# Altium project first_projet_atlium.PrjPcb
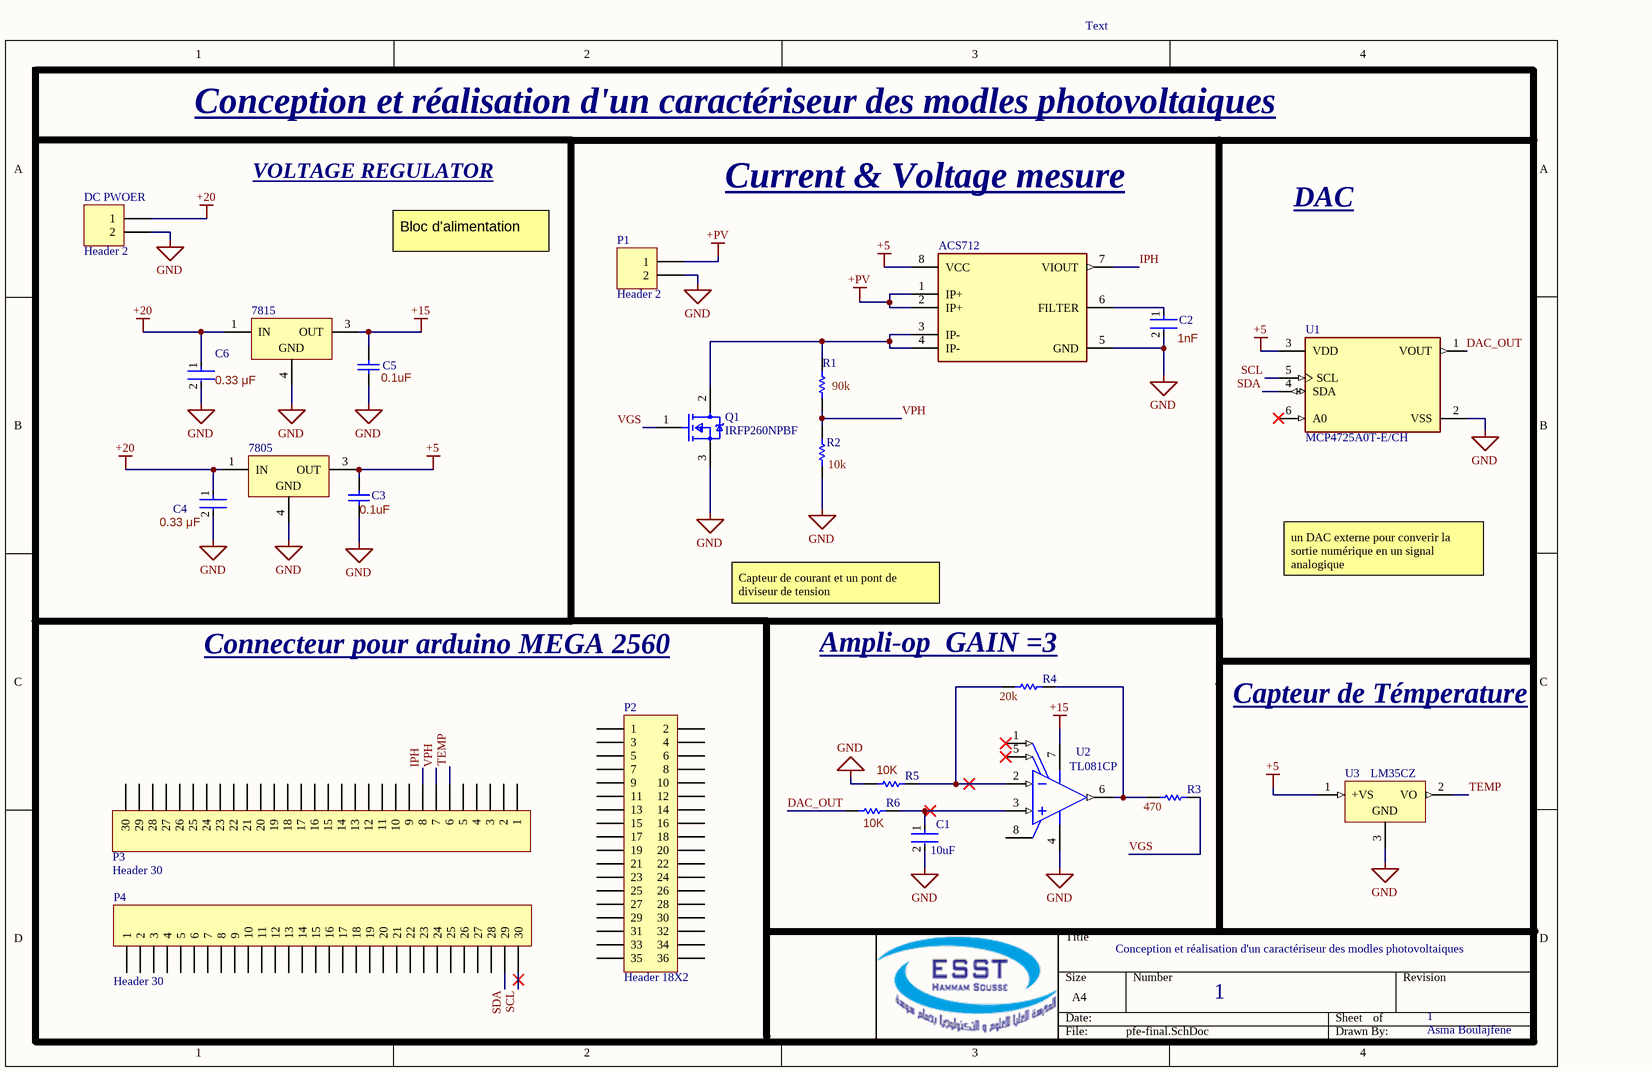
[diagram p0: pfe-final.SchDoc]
1 sheet, 24 parts. Net scope: global (net labels, ports and power ports of the same name join across sheets).
Board file: pfe-final.PcbDoc

## Sheet pfe-final.SchDoc: Conception et réalisation d'un caractériseur des modles photovoltaiques
size A4; ApprovedBy: Hanen Zormati; CheckedBy: Hanen Zormati; CompanyName: CRMN; DrawnBy: Asma Boulajfene; Engineer: Embedded System; DocumentNumber: 1; SheetNumber: 1; SheetTotal: 1

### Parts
7805  L7805CD2T-TR  [TO-263_M]  (value not drawn)
7815  L7815CD2T-TR  [TO-263_N]  (value not drawn)
ACS712  ACS712ELCTR-30A-T  [FP-LC-8-IPC_C]  (value not drawn)
C1  value 10uF  [FP-C0805C-DG-MFG]  (hidden comment: C0805C106K8PACTU)
C2  value 1nF  [FP-C0805C-DN-MFG]  (hidden comment: C0805C102J1GACTU)
C3  Capacitance: 0.1uF  [CAPC2013X135X45ML10T25]  (hidden comment: GRM21BR71H104KA01L)
C4  value 0.33 μF  [FP-C0805C-DN-MFG]  (hidden comment: C0805C334K5RACTU)
C5  Capacitance: 0.1uF  [CAPC2013X135X45ML10T25]  (hidden comment: GRM21BR71H104KA01L)
C6  value 0.33 μF  [FP-C0805C-DN-MFG]  (hidden comment: C0805C334K5RACTU)
DC_PWOER  Header 2  [HDR1X2]
P1  Header 2  [HDR1X2]
P2  Header 18X2  [HDR2X18]
P3  Header 30  [HDR1X30]
P4  Header 30  [HDR1X30]
Q1  IRFP260NPBF  [FP-PG-TO247-3-MFG]
R1  value 90k  [RESC0805(2012)_M]  (hidden comment: 150K 1% 0805(2012))
R2  value 10k  [RESC2013X60X35NL10T20]  (hidden comment: RC0805FR-0710KL)
R3  value 470  [RESC2013X60X35NL10T20]  (hidden comment: RC0805FR-0710KL)
R4  value 20k  [RESC2013X60X35NL10T20]  (hidden comment: RC0805FR-0710KL)
R5  value 10K  [RESC2013X60X35NL10T20]  (hidden comment: RC0805FR-0710KL)
R6  value 10K  [RESC2013X60X35NL10T20]  (hidden comment: RC0805FR-0710KL)
U1  MCP4725A0T-E/CH  [FP-C04-028-CHY-IPC_B]
U2  TL081CP  [P0008A]
U3  LM35CZ  [Z03A]

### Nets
+5: 7805.3(OUT) ACS712.8(VCC) C3.2 U1.3(VDD) U3.1(+VS)
+15: 7815.3(OUT) C5.2 U2.7(VCC+)
+20: 7805.1(IN) 7815.1(IN) C4.1 C6.1 DC_PWOER.1
+PV: ACS712.1(IP+) ACS712.2(IP+) P1.1
GND: 7805.4(GND) 7815.4(GND) ACS712.5(GND) C1.2 C2.2 C3.1 C4.2 C5.1 C6.2 DC_PWOER.2 P1.2 Q1.3(S) R2.1 R5.1 U1.2(VSS) U2.4(VCC-) U3.3(GND)
DAC_OUT: R6.1 U1.1(VOUT)
IPH: ACS712.7(VIOUT) P3.8
SCL: P4.30 U1.5(SCL)
SDA: P4.29 U1.4(SDA)
TEMP: P3.6 U3.2(VO)
VGS: Q1.1(G) R3.2
VPH: P3.7 R1.1 R2.2
NetACS712_3: ACS712.3(IP-) ACS712.4(IP-) Q1.2(D) R1.2
NetACS712_6: ACS712.6(FILTER) C2.1
NetC1_1: C1.1 R6.2 U2.3(IN+)
NetR3_1: R3.1 R4.2 U2.6(OUT)
NetR4_1: R4.1 R5.2 U2.2(IN-)

Not connected (* = marked no-connect by the designer): P2 1 2 3 4 5 6 7 8 9 10 11 12 13 14 15 16 17 18 19 20 21 22 23 24 25 26 27 28 29 30 31 32 33 34 35 36; P3 1 2 3 4 5 9 10 11 12 13 14 15 16 17 18 19 20 21 22 23 24 25 26 27 28 29 30; P4 1 2 3 4 5 6 7 8 9 10 11 12 13 14 15 16 17 18 19 20 21 22 23 24 25 26 27 28; U1 6(A0)*; U2 1(OFFSET_N1)* 5(OFFSET_N2)* 8(NC)

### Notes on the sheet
- Text
- Conception et réalisation d'un caractériseur des modles photovoltaiques
- VOLTAGE REGULATOR
- Current & Voltage mesure
- DAC
- Bloc d'alimentation
- Capteur de courant et un pont de diviseur de tension
- un DAC externe pour converir la sortie numérique en un signal analogique
- Connecteur pour arduino MEGA 2560
- (near R4) Ampli-op  GAIN =3
- Capteur de Témperature
- 1
- Asma Boulajfene

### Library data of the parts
7805 = CMP-0244-00213-1: Positive Voltage Regulator, 3-Pin D2PAK, Tape and Reel
7815 = CMP-0244-00179-1: Positive Voltage Regulator, 3-Pin D2PAK, Tape and Reel
ACS712 = CMP-2000-04990-2: SENSOR CURRENT HALL 30A AC/DC; Bandwidth: 80kHz; Max Supply Current: 13mA; Linearity: 1.5%; Operating Supply Voltage: 5V; Quiescent Current: 10mA; Number of Channels: 1; Polarity: Bidirectional; Min Supply Voltage: 4.5V; Response Time: 5us; Sensitivity: 66mV/A; Max Supply Voltage: 5.5V
C1 = CMP-2007-03243-2: CAP CER 10UF 10V X5R 0805; Manufacturer: Kemet; 3DS Part Number: 220-00001; Tolerance: 10%; Temperature Coefficient: 15%; Material: Ceramic
C2 = CMP-2007-00233-2: CAP CER 1000PF 100V C0G/NP0 0805; Manufacturer: KEMET; Capacitance: 1,000 pF; Temperature Coefficient: 30ppm/°C; Material: Ceramic; Tolerance: 0.05; Temperature Characteristic: C0G
C3 C5 = CMP-2100-03644-1: Chip Capacitor, 0.1 uF, +/- 10%, 50 V, -55 to 125 degC, 0805 (2012 Metric), RoHS, Tape and Reel; Manufacturer: Murata; Voltage: 50V; Insulation Resistance: 10GR; Dielectric Material: Ceramic; Dielectric: X7R
C4 C6 = CMP-1036-04607-3: CAP CER 0.33UF 50V X7R 0805; Manufacturer: KEMET; Temperature Coefficient: 30ppm/°C; Material: Ceramic; Tolerance: 0.1
DC_PWOER P1 = Header 2: Header, 2-Pin
P2 = Header 18X2: Header, 18-Pin, Dual row
P3 P4 = Header 30: Header, 30-Pin
Q1 = CMP-32901-000262-1: MOSFET N-CH 200V 50A TO247AC; Drain to Source Resistance: 40mR; Turn-On Delay Time: 17ns; Gate to Source Voltage (Vgs): 20V; Turn-Off Delay Time: 55ns; Max Power Dissipation: 300W; Element Configuration: Single; Input Capacitance: 4.057nF; Threshold Voltage: 4V
R1 = CMP-1013-00754-1: 150K 0.125W 1% 0805 (2012 Metric)  SMD; Case-EIA: 0805; Case-Metric: 2012
R2-R6 = CMP-1659-00013-4: Chip Resistor, 10 KOhm, +/- 1%, 0.125 W, -55 to 155 degC, 0805 (2012 Metric), RoHS, Tape and Reel; Manufacturer: Yageo; Voltage Rating: 150 V
U1 = CMP-0188-00760-3: IC DAC 12BIT V-OUT SOT23-6; Number of Outputs: 1; Supply Type: Single; Integral Nonlinearity (INL): 14.5LSB; Polarity: Unipolar; Number of Bits: 12; Min Supply Voltage: 2.7V; Output Type: Voltage; Settling Time: 6us; Max Supply Voltage: 5.5V; Nominal Supply Current: 210uA; Resolution: 12b; Interface: I2C; Input Offset Voltage (Vos): 1.1mV
U2 = CMP-0017-00937-2: JFET-Input Operational Amplifier, 7 to 36 V, 0 to 70 degC, 8-pin DIP (P8), Pb-Free (RoHS); Manufacturer: Texas Instruments; Rating: Military; GBW(Typ)(MHz): 3; Vio (25C)(Max)(mV): 15; CMRR(Min)(dB): 70; Slew Rate(Typ)(V/us): 13; IIB(Max)(pA): 400; Vn at 1kHz(Typ)(nV/rtHz): 18; Sub Family: General Purpose Amplifier, High Supply Voltage Amplifier (>=30V); Number of Channels: 1; Total Supply Voltage(Min)(+5V is 5, +/-5V is 10): 7; Total Supply Voltage(Max)(+5V is 5, +/-5V is 10): 36; Iq per channel(Max)(mA): 2.8
U3 = CMP-0066-00027-2: Precision Centigrade Temperature Sensor, 3-pin TO-92; Manufacturer: National Semiconductor; CompType: Temp Sensor IC; PowerWise: N; PackageTopMarking: NSXYTT*LM35*CZ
